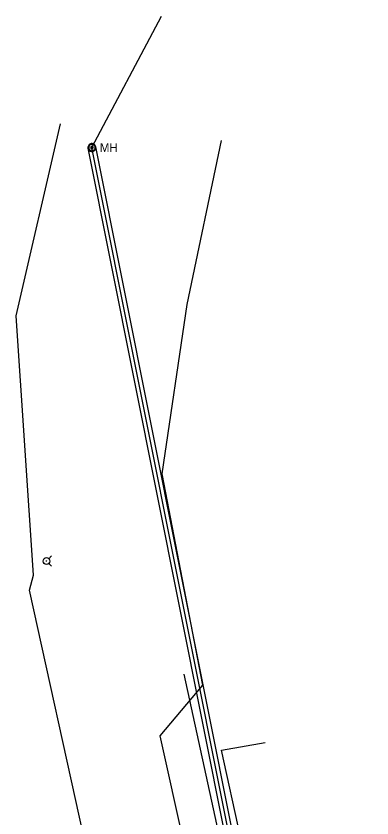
# Model space of a CAD drawing. Extents: x 600849 to 606371, y 330010 to 403088.
# Drawn here: x 604584 to 604857, y 339696 to 340313 of the extents above; entities that cross this region are included whole.
import ezdxf

# ---------------------------------------------------------------- set-up
doc = ezdxf.new("R2010")
doc.units = 0
for name, color, linetype in [('E_UTL_G_UG', 7, 'Continuous'), ('E_UTL_SAN', 7, 'Continuous'), ('E_UTL_SAN_UG_MMSD', 7, 'Continuous'), ('E_UTL_SAN_UG_OUTER_LIMITS', 7, 'Continuous'), ('E_UTL_W_UG', 7, 'Continuous'), ('E_UTL_WHydrant', 7, 'Continuous')]:
    doc.layers.add(name, color=color, linetype=linetype)

# ---------------------------------------------------------------- blocks, each defined once
blk = doc.blocks.new('ACAD_PROXY_ENTITY_1')
at = {"layer": 'E_UTL_SAN'}
for points in [[(1844102.4, 1030298.3), (1844102.2, 1030300.1), (1844101.7, 1030301.8), (1844100.9, 1030303.3), (1844099.8, 1030304.7), (1844098.5, 1030305.9), (1844096.9, 1030306.8), (1844095.3, 1030307.4), (1844093.5, 1030307.6), (1844091.7, 1030307.5), (1844090, 1030307.1), (1844088.4, 1030306.4), (1844087, 1030305.3), (1844085.7, 1030304.1), (1844084.8, 1030302.6), (1844084.1, 1030300.9), (1844083.8, 1030299.2), (1844083.8, 1030297.4), (1844084.1, 1030295.7), (1844084.8, 1030294), (1844085.7, 1030292.6), (1844087, 1030291.3), (1844088.4, 1030290.2), (1844090, 1030289.5), (1844091.7, 1030289.1), (1844093.5, 1030289), (1844095.3, 1030289.3), (1844096.9, 1030289.8), (1844098.5, 1030290.7), (1844099.8, 1030291.9), (1844100.9, 1030293.3), (1844101.7, 1030294.8), (1844102.2, 1030296.5), (1844102.4, 1030298.3)], [(1844100.5, 1030298.3), (1844100.4, 1030299.7), (1844100, 1030301.1), (1844099.3, 1030302.3), (1844098.5, 1030303.5), (1844097.4, 1030304.4), (1844096.2, 1030305.1), (1844094.8, 1030305.6), (1844093.4, 1030305.8), (1844092, 1030305.7), (1844090.6, 1030305.4), (1844089.3, 1030304.8), (1844088.2, 1030303.9), (1844087.2, 1030302.9), (1844086.4, 1030301.7), (1844085.9, 1030300.4), (1844085.6, 1030299), (1844085.6, 1030297.6), (1844085.9, 1030296.2), (1844086.4, 1030294.9), (1844087.2, 1030293.7), (1844088.2, 1030292.7), (1844089.3, 1030291.9), (1844090.6, 1030291.3), (1844092, 1030290.9), (1844093.4, 1030290.9), (1844094.8, 1030291.1), (1844096.2, 1030291.5), (1844097.4, 1030292.2), (1844098.5, 1030293.2), (1844099.3, 1030294.3), (1844100, 1030295.5), (1844100.4, 1030296.9), (1844100.5, 1030298.3)], [(1844095.9, 1030298.3), (1844095.8, 1030298.8), (1844095.7, 1030299.3), (1844095.4, 1030299.8), (1844095.1, 1030300.2), (1844094.7, 1030300.6), (1844094.2, 1030300.9), (1844093.7, 1030301), (1844093.2, 1030301.1), (1844092.7, 1030301.1), (1844092.2, 1030300.9), (1844091.7, 1030300.7), (1844091.2, 1030300.4), (1844090.9, 1030300), (1844090.6, 1030299.6), (1844090.4, 1030299.1), (1844090.3, 1030298.6), (1844090.3, 1030298), (1844090.4, 1030297.5), (1844090.6, 1030297), (1844090.9, 1030296.6), (1844091.2, 1030296.2), (1844091.7, 1030295.9), (1844092.2, 1030295.7), (1844092.7, 1030295.5), (1844093.2, 1030295.5), (1844093.7, 1030295.6), (1844094.2, 1030295.8), (1844094.7, 1030296), (1844095.1, 1030296.4), (1844095.4, 1030296.8), (1844095.7, 1030297.3), (1844095.8, 1030297.8), (1844095.9, 1030298.3)]]:
    blk.add_lwpolyline(points, dxfattribs=at)
blk.add_text('MH', height=20.12, dxfattribs=at).set_placement((1844111.7, 1030288.2))
blk = doc.blocks.new('HYD')
at = {"layer": 'E_UTL_WHydrant'}
for p, q in [((-11.7, 11.7), (-25.4, 25.4)), ((11.7, 11.7), (25.4, 25.4))]:
    blk.add_line(p, q, dxfattribs=at)
for radius in [16.7, 1.28]:
    blk.add_circle((0, 0), radius, dxfattribs=at)

msp = doc.modelspace()

# ---------------------------------------------------------------- linework, layer by layer
at = {"layer": 'E_UTL_G_UG'}
for p, q in [((604676.2, 339500.02), (604594.23, 339871.46)), ((604741.72, 339748.42), (604775.4, 339754.32)), ((604795, 339507.19), (604741.72, 339748.42))]:
    msp.add_line(p, q, dxfattribs=at)
for points in [[(604594.23, 339871.46), (604597.4, 339882.96), (604583.89, 340082.56), (604618.09, 340230.44)], [(604751.42, 339503.86), (604694.75, 339759.52), (604727.4, 339798.39), (604696.08, 339960.93), (604715.5, 340091.34), (604741.91, 340217.55)]]:
    msp.add_lwpolyline(points, dxfattribs=at)
at = {"layer": 'E_UTL_SAN_UG_MMSD'}
for p, q in [((604642.2, 340212.1), (604695.78, 340313.31)), ((604854.51, 339147.21), (604642.2, 340212.1))]:
    msp.add_line(p, q, dxfattribs=at)
at = {"layer": 'E_UTL_SAN_UG_OUTER_LIMITS'}
for p, q in [((604857.47, 339147.72), (604645.14, 340212.68)), ((604851.55, 339146.7), (604639.25, 340211.51))]:
    msp.add_line(p, q, dxfattribs=at)
at = {"layer": 'E_UTL_W_UG'}
msp.add_lwpolyline([(604805.77, 339390.57), (604775.12, 339521.94), (604713.1, 339806.92)], dxfattribs=at)

# ---------------------------------------------------------------- block references
at = {"layer": 'E_UTL_SAN', "xscale": 0.32808333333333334, "yscale": 0.32808333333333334}
msp.add_blockref('ACAD_PROXY_ENTITY_1', (-374, 2188.39), dxfattribs=at)
at = {"layer": 'E_UTL_WHydrant', "xscale": 0.15485533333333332, "yscale": 0.15485533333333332, "rotation": -90.00000000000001}
msp.add_blockref('HYD', (604607.25, 339893.92), dxfattribs=at)

doc.saveas('drawing.dxf')
